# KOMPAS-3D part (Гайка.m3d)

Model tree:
1. Эскиз:1
2. Операция выдавливания:1
     Расстояние 1 = 32
3. Эскиз:2
4. Вырезать элемент выдавливания:1
     Расстояние 1 = 32
5. Эскиз:3
6. Операция выдавливания:2
     Расстояние 1 = 30; Расстояние 2 = 2
7. Условное изображение резьбы:1
     Длина резьбы = 32; Шаг резьбы = 5; Номинальный диаметр резьбы = 28
8. Эскиз:4
9. Вырезать элемент выдавливания:2
     Расстояние 2 = 40; Расстояние 1 = 2
10. Фаска:1
     Угол = 45; Длина 1 = 1; Длина 2 = 1
